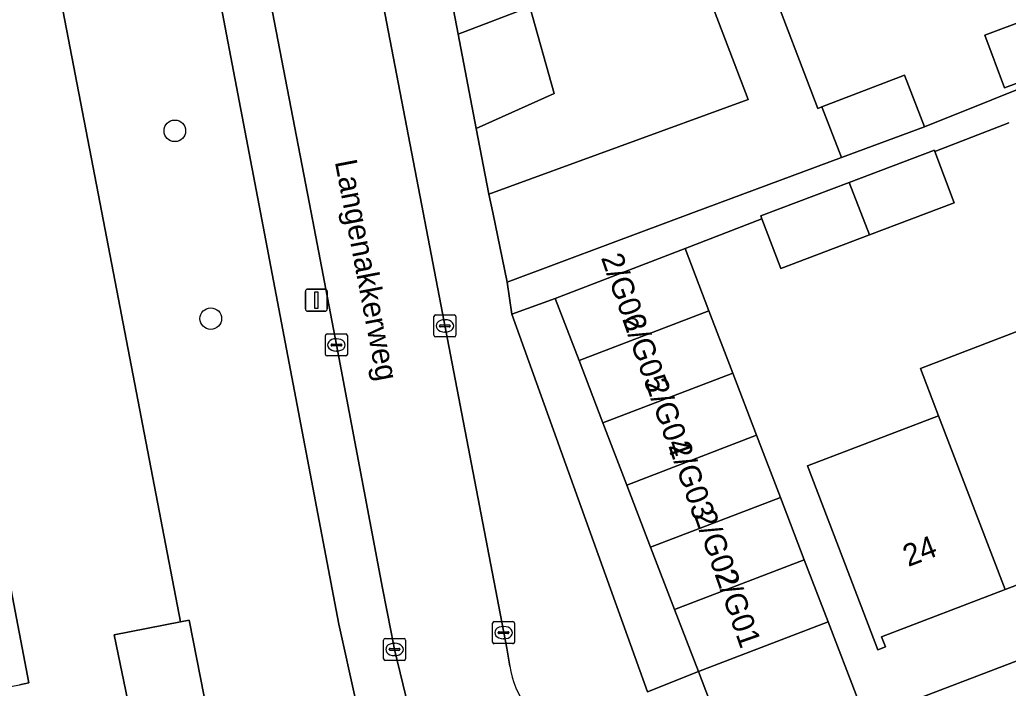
# Model space of a CAD drawing. Extents: x 159262 to 160143, y 383399 to 384319.
# Drawn here: x 159361.44 to 159406.24, y 383728.43 to 383758.75 of the extents above; entities that cross this region are included whole.
import ezdxf

# ---------------------------------------------------------------- set-up
doc = ezdxf.new("R2010")
doc.units = 0
for name, color, linetype in [('IMGEO_Boom', 7, 'Continuous'), ('IMGEO_Erf', 7, 'Continuous'), ('IMGEO_Groenvoorziening', 7, 'Continuous'), ('IMGEO_Kolk', 7, 'Continuous'), ('IMGEO_Lichtmast', 7, 'Continuous'), ('IMGEO_Openbare_ruimte_label', 7, 'Continuous'), ('IMGEO_Pand', 7, 'Continuous'), ('IMGEO_Pand_nummerreeks', 7, 'Continuous'), ('IMGEO_Rijbaan_lokaal_open', 7, 'Continuous'), ('IMGEO_Voetpad_open', 7, 'Continuous')]:
    doc.layers.add(name, color=color, linetype=linetype)

msp = doc.modelspace()

# ---------------------------------------------------------------- linework, layer by layer
at = {"layer": 'IMGEO_Boom'}
for centre in [(159368.464, 383753.708), (159370.093, 383745.193)]:
    msp.add_circle(centre, 0.489, dxfattribs=at)
at = {"layer": 'IMGEO_Erf'}
for points in [[(159411.906, 383769.536), (159406.156, 383767.336), (159400.339, 383765.112), (159401.208, 383762.87), (159395.493, 383760.684), (159395.351, 383760.63), (159397.605, 383754.719), (159397.792, 383754.791), (159401.541, 383756.23), (159402.437, 383753.896), (159417.698, 383760.02)], [(159379.857, 383765.664), (159381.308, 383758.091), (159384.559, 383759.339), (159385.65, 383755.4), (159382.115, 383753.813), (159382.7, 383750.83), (159394.45, 383755.134), (159391.879, 383761.875), (159389.07, 383760.801), (159389.22, 383760.409), (159388.866, 383760.273), (159388.72, 383760.653), (159385.981, 383759.602), (159383.927, 383764.958)], [(159351.446, 383675.234), (159386.849, 383686.19), (159381.893, 383711.852), (159381.778, 383712.195), (159377.368, 383711.323), (159375.842, 383719.035), (159375.163, 383722.468), (159374.993, 383723.328), (159374.691, 383724.853), (159374.193, 383727.372), (159370.092, 383726.561), (159369.797, 383728.052), (159366.431, 383727.422), (159365.715, 383730.856), (159368.719, 383731.446), (159365.154, 383750), (159362.754, 383762.488)], [(159406.26, 383754.07), (159402.913, 383752.769), (159403.795, 383750.447), (159399.944, 383748.986), (159395.928, 383747.461), (159395.071, 383749.719), (159391.588, 383748.365), (159392.669, 383745.544), (159393.75, 383742.722), (159394.832, 383739.901), (159395.913, 383737.08), (159396.994, 383734.258), (159398.075, 383731.437), (159399.417, 383727.934), (159393.534, 383725.68), (159392.192, 383729.183), (159389.893, 383728.272)], [(159395.668, 383725.482), (159397.024, 383726), (159410.124, 383731.006), (159460.07, 383750), (159471.013, 383754.202)], [(159357.766, 383750), (159361.846, 383728.67), (159361.423, 383728.589)], [(159397.138, 383738.516), (159403.079, 383740.79), (159402.259, 383742.935), (159408.042, 383745.149)], [(159411.688, 383735.046), (159406.095, 383732.905), (159400.501, 383730.764), (159400.675, 383730.309), (159400.33, 383730.176), (159398.542, 383734.846), (159397.138, 383738.516)]]:
    msp.add_lwpolyline(points, dxfattribs=at)
msp.add_lwpolyline([(159413.707, 383758.494), (159410.679, 383757.367), (159406.071, 383755.652), (159405.179, 383758.048), (159409.26, 383759.567), (159412.816, 383760.89)], close=True, dxfattribs=at)
at = {"layer": 'IMGEO_Groenvoorziening'}
msp.add_lwpolyline([(159369.491, 383768.488), (159368.305, 383769.288), (159362.851, 383772.897), (159361.511, 383770.836), (159362.132, 383767.578), (159362.599, 383765.517), (159364.014, 383765.794), (159364.565, 383762.838), (159363.152, 383762.562), (159362.754, 383762.488), (159365.154, 383750), (159368.719, 383731.446), (159369.111, 383731.523), (159369.797, 383728.052), (159370.092, 383726.561), (159374.193, 383727.372), (159376.664, 383727.861), (159375.895, 383731.337), (159372.341, 383750), (159369.458, 383765.136)], dxfattribs=at)
at = {"layer": 'IMGEO_Kolk'}
for p, q in [((159380.205, 383744.435), (159380.205, 383745.287)), ((159380.28, 383745.361), (159381.132, 383745.361)), ((159380.693, 383745.141), (159380.718, 383745.141)), ((159381.206, 383745.287), (159381.206, 383744.435)), ((159380.464, 383744.855), (159380.464, 383744.867)), ((159380.902, 383744.818), (159380.504, 383744.818)), ((159380.507, 383744.904), (159380.905, 383744.904)), ((159380.948, 383744.867), (159380.948, 383744.855)), ((159375.286, 383743.572), (159375.286, 383744.424)), ((159375.361, 383744.498), (159376.213, 383744.498)), ((159375.774, 383744.278), (159375.799, 383744.278)), ((159376.287, 383744.424), (159376.287, 383743.572)), ((159381.132, 383744.361), (159380.28, 383744.361)), ((159380.716, 383744.581), (159380.691, 383744.581)), ((159375.545, 383743.992), (159375.545, 383744.004)), ((159375.983, 383743.955), (159375.585, 383743.955)), ((159375.588, 383744.041), (159375.986, 383744.041)), ((159375.797, 383743.718), (159375.772, 383743.718)), ((159376.029, 383744.004), (159376.029, 383743.992)), ((159376.213, 383743.498), (159375.361, 383743.498)), ((159382.864, 383730.526), (159382.864, 383731.378)), ((159382.939, 383731.452), (159383.791, 383731.452)), ((159383.352, 383731.232), (159383.377, 383731.232)), ((159383.865, 383731.378), (159383.865, 383730.526)), ((159383.123, 383730.946), (159383.123, 383730.958)), ((159383.561, 383730.909), (159383.163, 383730.909)), ((159383.166, 383730.995), (159383.564, 383730.995)), ((159383.607, 383730.958), (159383.607, 383730.946)), ((159377.924, 383729.766), (159377.924, 383730.618)), ((159377.999, 383730.692), (159378.851, 383730.692)), ((159378.412, 383730.472), (159378.437, 383730.472)), ((159378.925, 383730.618), (159378.925, 383729.766)), ((159383.791, 383730.452), (159382.939, 383730.452)), ((159383.375, 383730.672), (159383.35, 383730.672)), ((159378.183, 383730.186), (159378.183, 383730.198)), ((159378.621, 383730.149), (159378.223, 383730.149)), ((159378.226, 383730.235), (159378.624, 383730.235)), ((159378.435, 383729.912), (159378.41, 383729.912)), ((159378.667, 383730.198), (159378.667, 383730.186)), ((159378.851, 383729.692), (159377.999, 383729.692))]:
    msp.add_line(p, q, dxfattribs=at)
for points in [[(159380.205, 383744.435), (159380.205, 383745.287)], [(159380.28, 383745.361), (159381.132, 383745.361)], [(159381.206, 383745.287), (159381.206, 383744.435)], [(159375.286, 383743.572), (159375.286, 383744.424)], [(159375.361, 383744.498), (159376.213, 383744.498)], [(159376.287, 383744.424), (159376.287, 383743.572)], [(159381.132, 383744.361), (159380.28, 383744.361)], [(159376.213, 383743.498), (159375.361, 383743.498)], [(159382.864, 383730.526), (159382.864, 383731.378)], [(159382.939, 383731.452), (159383.791, 383731.452)], [(159383.865, 383731.378), (159383.865, 383730.526)], [(159377.924, 383729.766), (159377.924, 383730.618)], [(159377.999, 383730.692), (159378.851, 383730.692)], [(159378.925, 383730.618), (159378.925, 383729.766)], [(159383.791, 383730.452), (159382.939, 383730.452)], [(159378.851, 383729.692), (159377.999, 383729.692)]]:
    msp.add_lwpolyline(points, dxfattribs=at)
for centre, radius, start, end in [((159380.282, 383745.285), 0.0765, 91.552, 178.448), ((159380.282, 383745.285), 0.0765, 91.552, 178.448), ((159381.13, 383745.285), 0.0765, 1.552, 88.448), ((159381.13, 383745.285), 0.0765, 1.552, 88.448), ((159380.504, 383744.864), 0.0403, 85.8775, 175.7526), ((159380.501, 383744.854), 0.0366, 178.938, 274.7102), ((159380.905, 383744.861), 0.043, 264.8664, 352.4533), ((159380.909, 383744.866), 0.0386, 1.7309, 96.639), ((159375.363, 383744.422), 0.0765, 91.552, 178.448), ((159375.363, 383744.422), 0.0765, 91.552, 178.448), ((159376.211, 383744.422), 0.0765, 1.552, 88.448), ((159376.211, 383744.422), 0.0765, 1.552, 88.448), ((159380.282, 383744.437), 0.0765, 181.552, 268.448), ((159380.282, 383744.437), 0.0765, 181.552, 268.448), ((159381.13, 383744.437), 0.0765, 271.552, 358.448), ((159381.13, 383744.437), 0.0765, 271.552, 358.448), ((159375.585, 383744.001), 0.0403, 85.8775, 175.7526), ((159375.582, 383743.991), 0.0366, 178.938, 274.7102), ((159375.986, 383743.998), 0.043, 264.8664, 352.4533), ((159375.99, 383744.003), 0.0386, 1.7309, 96.639), ((159375.363, 383743.574), 0.0765, 181.552, 268.448), ((159375.363, 383743.574), 0.0765, 181.552, 268.448), ((159376.211, 383743.574), 0.0765, 271.552, 358.448), ((159376.211, 383743.574), 0.0765, 271.552, 358.448), ((159382.941, 383731.376), 0.0765, 91.552, 178.448), ((159382.941, 383731.376), 0.0765, 91.552, 178.448), ((159383.789, 383731.376), 0.0765, 1.552, 88.448), ((159383.789, 383731.376), 0.0765, 1.552, 88.448), ((159383.163, 383730.955), 0.0403, 85.8775, 175.7526), ((159383.16, 383730.945), 0.0366, 178.938, 274.7102), ((159383.564, 383730.952), 0.043, 264.8664, 352.4533), ((159383.568, 383730.957), 0.0386, 1.7309, 96.639), ((159378.001, 383730.616), 0.0765, 91.552, 178.448), ((159378.001, 383730.616), 0.0765, 91.552, 178.448), ((159378.849, 383730.616), 0.0765, 1.552, 88.448), ((159378.849, 383730.616), 0.0765, 1.552, 88.448), ((159382.941, 383730.528), 0.0765, 181.552, 268.448), ((159382.941, 383730.528), 0.0765, 181.552, 268.448), ((159383.789, 383730.528), 0.0765, 271.552, 358.448), ((159383.789, 383730.528), 0.0765, 271.552, 358.448), ((159378.223, 383730.195), 0.0403, 85.8775, 175.7526), ((159378.22, 383730.185), 0.0366, 178.938, 274.7102), ((159378.624, 383730.192), 0.043, 264.8664, 352.4533), ((159378.628, 383730.197), 0.0386, 1.7309, 96.639), ((159378.001, 383729.768), 0.0765, 181.552, 268.448), ((159378.001, 383729.768), 0.0765, 181.552, 268.448), ((159378.849, 383729.768), 0.0765, 271.552, 358.448), ((159378.849, 383729.768), 0.0765, 271.552, 358.448)]:
    msp.add_arc(centre, radius, start, end, dxfattribs=at)
for centre, major_axis, ratio, start_param, end_param in [((159380.692, 383744.861), (-0.387, 0.002), 0.722429, 4.712389, 7.853982), ((159380.717, 383744.861), (-0.39, 0.002), 0.717154, 1.570796, 4.712389), ((159375.773, 383743.998), (-0.387, 0.002), 0.722429, 4.712389, 7.853982), ((159375.798, 383743.998), (-0.39, 0.002), 0.717154, 1.570796, 4.712389), ((159383.351, 383730.952), (-0.387, 0.002), 0.722429, 4.712389, 7.853982), ((159383.376, 383730.952), (-0.39, 0.002), 0.717154, 1.570796, 4.712389), ((159378.411, 383730.192), (-0.387, 0.002), 0.722429, 4.712389, 7.853982), ((159378.436, 383730.192), (-0.39, 0.002), 0.717154, 1.570796, 4.712389)]:
    msp.add_ellipse(centre, major_axis=major_axis, ratio=ratio, start_param=start_param, end_param=end_param, dxfattribs=at)
at = {"layer": 'IMGEO_Lichtmast'}
for p, q in [((159374.382, 383745.629), (159374.382, 383746.429)), ((159374.382, 383746.429), (159374.382, 383745.629)), ((159374.482, 383746.529), (159375.272, 383746.529)), ((159375.272, 383746.529), (159374.482, 383746.529)), ((159375.372, 383746.429), (159375.372, 383745.629)), ((159375.372, 383745.629), (159375.372, 383746.429)), ((159375.272, 383745.529), (159374.482, 383745.529)), ((159374.482, 383745.529), (159375.272, 383745.529))]:
    msp.add_line(p, q, dxfattribs=at)
msp.add_lwpolyline([(159374.802, 383746.404), (159374.952, 383746.404), (159374.952, 383745.654), (159374.802, 383745.654), (159374.802, 383746.404)], dxfattribs=at)
for centre, start, end in [((159374.482, 383746.429), 90, 180), ((159374.482, 383746.429), 90, 180), ((159375.272, 383746.429), 0, 90), ((159375.272, 383746.429), 360, 90), ((159374.482, 383745.629), 180, 270), ((159374.482, 383745.629), 180, 270), ((159375.272, 383745.629), 270, 0), ((159375.272, 383745.629), 270, 0)]:
    msp.add_arc(centre, 0.1, start, end, dxfattribs=at)
at = {"layer": 'IMGEO_Pand'}
for points in [[(159391.678, 383770.585), (159386.133, 383768.456), (159385.945, 383768.945), (159385.588, 383768.807), (159386.663, 383766.007), (159383.927, 383764.958), (159385.981, 383759.602), (159388.72, 383760.653), (159388.866, 383760.273), (159389.22, 383760.409), (159389.07, 383760.801), (159391.879, 383761.875), (159394.45, 383755.134), (159382.7, 383750.83), (159382.871, 383750), (159383.52, 383746.85), (159388.206, 383748.595), (159391.978, 383750), (159398.686, 383752.499), (159397.792, 383754.791), (159397.605, 383754.719), (159395.351, 383760.63), (159395.493, 383760.684), (159394.619, 383762.923)], [(159410.679, 383757.367), (159410.258, 383758.42), (159409.329, 383758.049), (159408.876, 383759.184), (159409.339, 383759.369), (159409.26, 383759.567), (159405.179, 383758.048), (159406.071, 383755.652)], [(159381.308, 383758.091), (159382.115, 383753.813), (159385.65, 383755.4), (159384.559, 383759.339)], [(159344.704, 383730.975), (159345.759, 383725.591), (159354.54, 383727.272), (159361.423, 383728.589), (159361.846, 383728.67), (159357.766, 383750), (159356.294, 383757.697), (159350.703, 383756.598), (159341.398, 383754.835), (159342.325, 383750), (159344.839, 383736.882), (159345.562, 383733.106), (159345.686, 383732.457), (159345.922, 383731.228)], [(159398.686, 383752.499), (159402.437, 383753.896), (159401.541, 383756.23), (159397.792, 383754.791)], [(159402.913, 383752.769), (159402.889, 383752.833), (159399.032, 383751.37), (159399.944, 383748.986), (159403.795, 383750.447)], [(159399.032, 383751.37), (159395.022, 383749.847), (159395.071, 383749.719), (159395.928, 383747.461), (159399.944, 383748.986)], [(159392.669, 383745.544), (159391.588, 383748.365), (159385.705, 383746.111), (159386.786, 383743.289)], [(159387.867, 383740.468), (159393.75, 383742.722), (159392.669, 383745.544), (159386.786, 383743.289)], [(159408.859, 383743.002), (159408.042, 383745.149), (159402.259, 383742.935), (159403.079, 383740.79), (159406.095, 383732.905), (159411.688, 383735.046), (159411.855, 383734.61), (159412.05, 383734.685)], [(159387.867, 383740.468), (159388.949, 383737.647), (159394.832, 383739.901), (159393.75, 383742.722)], [(159403.079, 383740.79), (159397.138, 383738.516), (159398.542, 383734.846), (159400.33, 383730.176), (159400.675, 383730.309), (159400.501, 383730.764), (159406.095, 383732.905)], [(159390.03, 383734.825), (159395.913, 383737.08), (159394.832, 383739.901), (159388.949, 383737.647)], [(159390.03, 383734.825), (159391.111, 383732.004), (159396.994, 383734.258), (159395.913, 383737.08)], [(159391.111, 383732.004), (159392.192, 383729.183), (159398.075, 383731.437), (159396.994, 383734.258)], [(159368.719, 383731.446), (159365.715, 383730.856), (159366.431, 383727.422), (159369.797, 383728.052), (159369.111, 383731.523)], [(159398.075, 383731.437), (159392.192, 383729.183), (159393.534, 383725.68), (159399.417, 383727.934)]]:
    msp.add_lwpolyline(points, close=True, dxfattribs=at)
at = {"layer": 'IMGEO_Rijbaan_lokaal_open'}
for points in [[(159371.76, 383765.311), (159371.919, 383764.35), (159372.557, 383760.833), (159374.636, 383750), (159375.788, 383743.999), (159377.881, 383732.974), (159378.274, 383730.973), (159378.426, 383730.192), (159379.171, 383727.071)], [(159379.722, 383750), (159377.399, 383762.124), (159376.989, 383764.32)], [(159383.651, 383729.438), (159383.507, 383730.246), (159379.722, 383750)]]:
    msp.add_lwpolyline(points, dxfattribs=at)
msp.add_arc((159387.772, 383730.042), 4.166, 188.3376, 244.5733, dxfattribs=at)
at = {"layer": 'IMGEO_Voetpad_open'}
for points in [[(159375.788, 383743.999), (159374.636, 383750), (159372.557, 383760.833), (159371.919, 383764.35), (159371.76, 383765.311)], [(159383.732, 383745.39), (159383.52, 383746.85), (159382.871, 383750), (159382.7, 383750.83), (159382.115, 383753.813), (159381.308, 383758.091), (159379.857, 383765.664)], [(159369.458, 383765.136), (159372.341, 383750), (159375.895, 383731.337), (159376.664, 383727.861), (159376.89, 383726.839), (159377.147, 383726.069), (159379.171, 383727.071), (159378.426, 383730.192), (159378.274, 383730.973), (159377.881, 383732.974), (159375.788, 383743.999)], [(159376.989, 383764.32), (159377.399, 383762.124), (159379.722, 383750), (159383.507, 383730.246), (159383.651, 383729.438)], [(159417.698, 383760.02), (159402.437, 383753.896), (159398.686, 383752.499), (159391.978, 383750), (159388.206, 383748.595), (159383.52, 383746.85), (159383.732, 383745.39), (159385.705, 383746.111), (159391.588, 383748.365), (159395.071, 383749.719), (159395.022, 383749.847), (159399.032, 383751.37), (159402.889, 383752.833), (159402.913, 383752.769), (159406.26, 383754.07)], [(159471.013, 383754.202), (159460.07, 383750), (159410.124, 383731.006), (159397.024, 383726), (159398.217, 383722.877), (159398.531, 383723.111), (159398.805, 383723.383), (159399.019, 383723.733), (159399.395, 383724.672)], [(159389.893, 383728.272), (159383.732, 383745.39)]]:
    msp.add_lwpolyline(points, dxfattribs=at)
msp.add_lwpolyline([(159389.893, 383728.272), (159392.192, 383729.183), (159391.111, 383732.004), (159390.03, 383734.825), (159388.949, 383737.647), (159387.867, 383740.468), (159386.786, 383743.289), (159385.705, 383746.111), (159383.732, 383745.39)], close=True, dxfattribs=at)
msp.add_arc((159387.772, 383730.042), 4.166, 188.3376, 244.5733, dxfattribs=at)

# ---------------------------------------------------------------- texts
at = {"layer": 'IMGEO_Openbare_ruimte_label'}
msp.add_text('Langenakkerweg', height=1, rotation=280.8379, dxfattribs=at).set_placement((159375.712, 383752.311))
at = {"layer": 'IMGEO_Pand_nummerreeks'}
for s, rotation, p in [('2/G06', 289.3312, (159387.771, 383747.956)), ('2/G05', 289.3312, (159388.734, 383745.176)), ('2/G04', 289.3312, (159389.777, 383742.276)), ('2/G03', 289.3312, (159390.822, 383739.427)), ('2/G02', 289.3312, (159391.972, 383736.312)), ('24', 20.9876, (159401.703, 383733.924)), ('2/G01', 289.3312, (159392.917, 383733.619))]:
    msp.add_text(s, height=1, rotation=rotation, dxfattribs=at).set_placement(p)

doc.saveas('drawing.dxf')
